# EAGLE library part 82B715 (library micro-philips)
I2C bus extender
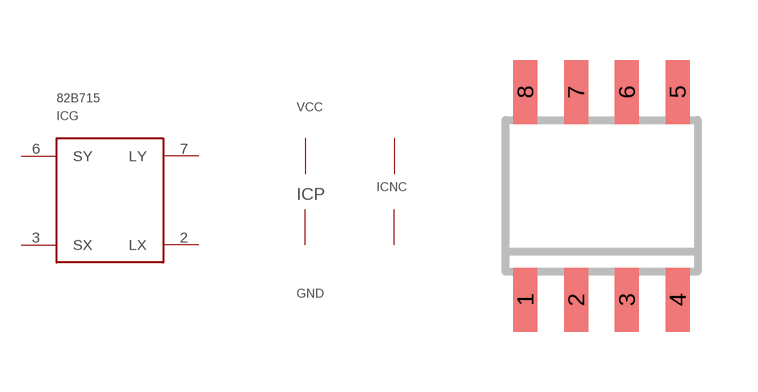
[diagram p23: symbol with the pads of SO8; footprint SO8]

Designator prefix IC; gates G=82B715 P=PWR2 NC=NC2

## 82B715TD (MPN: P82B715TD,118; OC_FARNELL: 1627047; OC_NEWARK: 70R8457)  [SO8]
1  NC:NC  nc
2  G:LX
3  G:SX
4  P:GND  pwr
5  NC:NC  nc
6  G:SY
7  G:LY
8  P:VCC  pwr

## Footprint SO8 (pad centres in mm)
SO8: plastic small outline package; 8 leads; body width 3.9 mm Source: http://www.nxp.com/documents/data_sheet/PCA82C250.pdf
smd 0.6 x 1.6: 1 -1.905,-2.6; 2 -0.635,-2.6; 3 0.635,-2.6; 4 1.905,-2.6; 5 1.905,2.6; 6 0.635,2.6; 7 -0.635,2.6; 8 -1.905,2.6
